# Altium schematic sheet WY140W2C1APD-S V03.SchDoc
size A2; CompanyName: 英集芯科技; DrawnBy: hjz
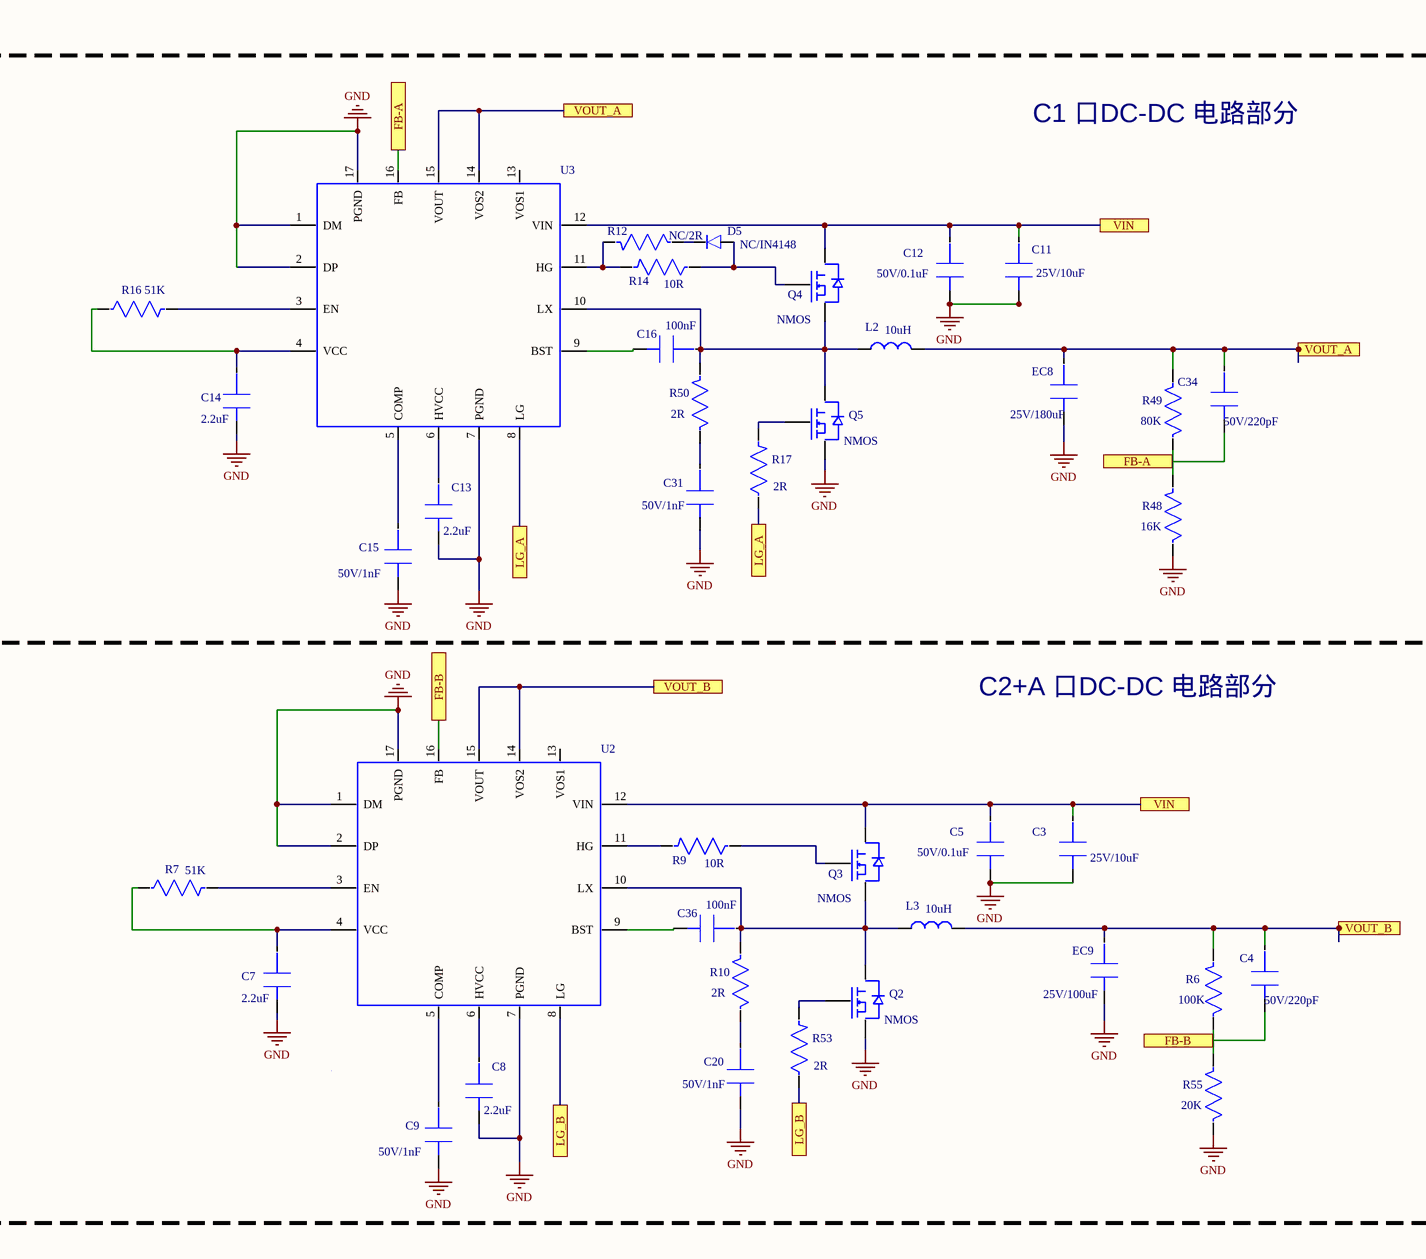
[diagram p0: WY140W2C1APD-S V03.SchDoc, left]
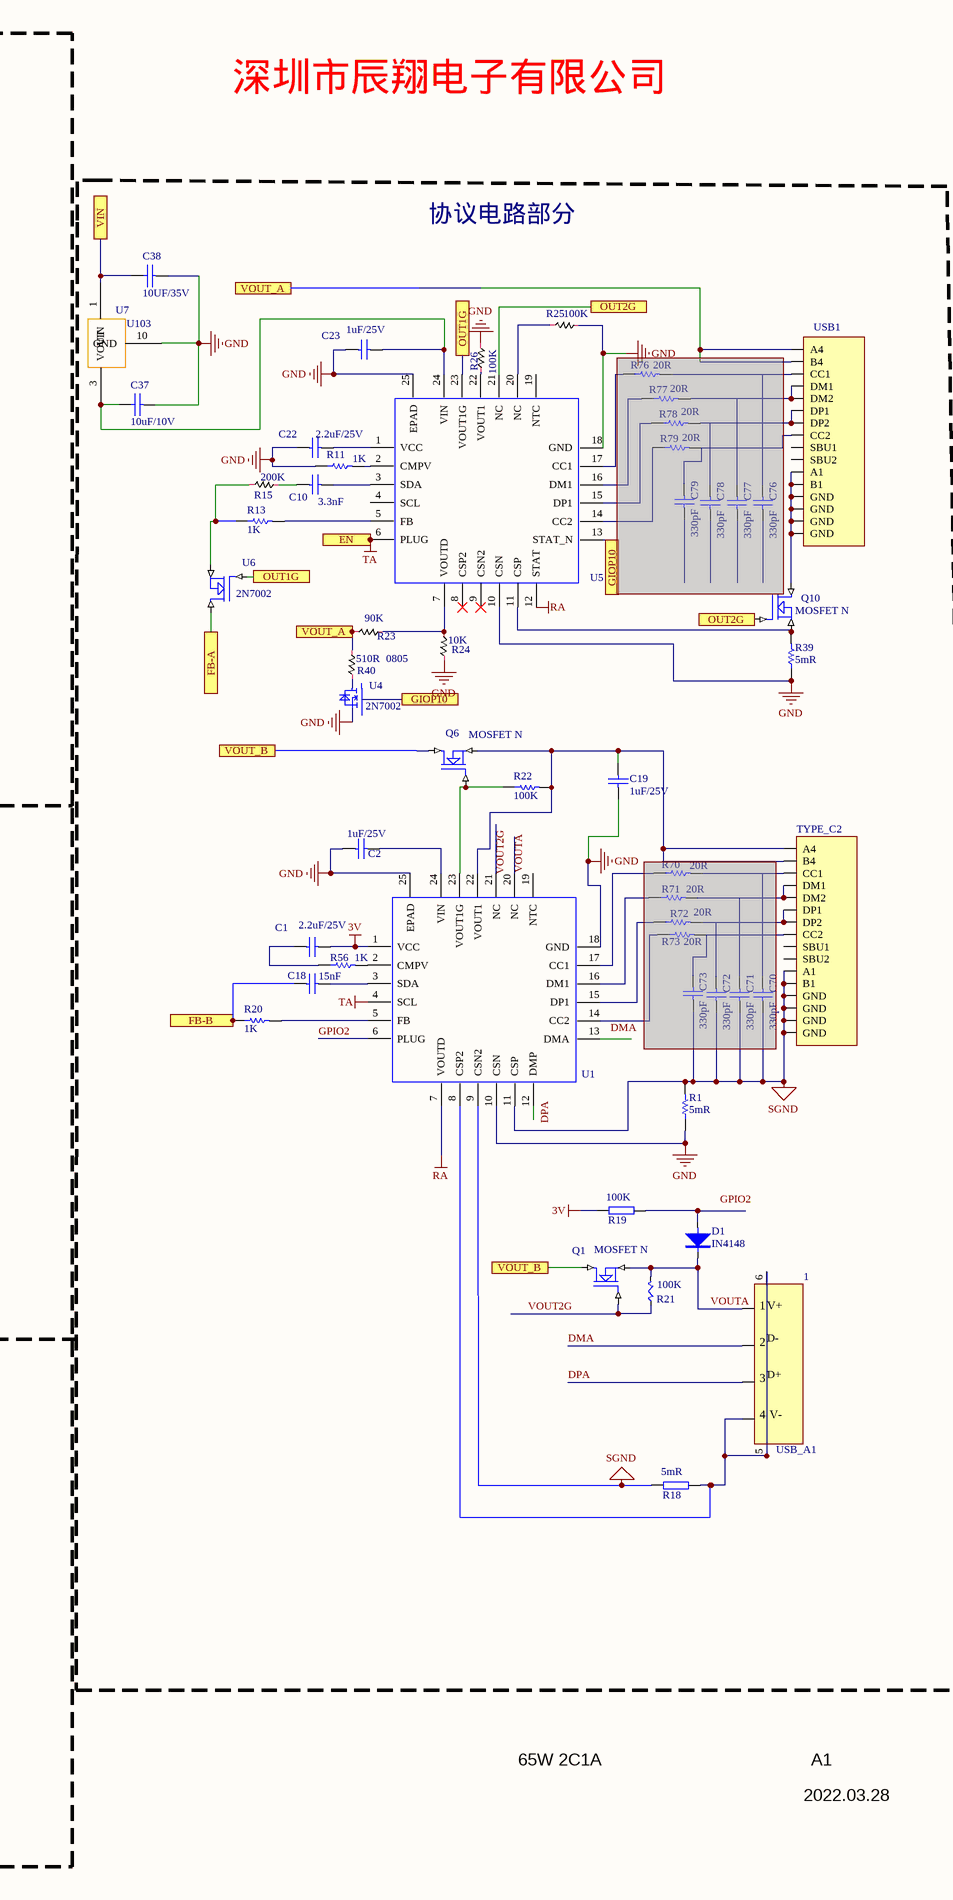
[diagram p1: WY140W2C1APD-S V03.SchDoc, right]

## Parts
1  USB_A1
C1  value 2.2uF/25V  [C0603]  (hidden comment: Cap)
C2  value 1uF/25V  [C0603]  (hidden comment: Cap)
C3  value 25V/10uF  [C0805]  (hidden comment: 0.1uF)
C4  value 50V/220pF  [C0805]  (hidden comment: 0.1uF)
C5  value 50V/0.1uF  [C0805]  (hidden comment: 0.1uF)
C7  2.2uF  [C0603]
C8  2.2uF  [C0603]
C9  value 50V/1nF  [C0603]  (hidden comment: 1nF)
C10  value 3.3nF  [C0603]  (hidden comment: Cap)
C11  value 25V/10uF  [C0805]  (hidden comment: 0.1uF)
C12  value 50V/0.1uF  [C0805]  (hidden comment: 0.1uF)
C13  2.2uF  [C0603]
C14  2.2uF  [C0603]
C15  value 50V/1nF  [C0603]  (hidden comment: 1nF)
C16  value 100nF  [C0603]  (hidden comment: 2.2uF)
C18  value 15nF  [C0603]  (hidden comment: Cap)
C19  value 1uF/25V  [C0603]  (hidden comment: Cap)
C20  value 50V/1nF  [C0603]  (hidden comment: 1nF)
C22  value 2.2uF/25V  [C0603]  (hidden comment: Cap)
C23  value 1uF/25V  [C0603]  (hidden comment: Cap)
C31  value 50V/1nF  [C0603]  (hidden comment: 1nF)
C34  value 50V/220pF  [C0805]  (hidden comment: 0.1uF)
C36  value 100nF  [C0603]  (hidden comment: 2.2uF)
C37  10uF/10V  [1206A]
C38  10UF/35V  [1206A]
C70  value 330pF  [C0603]  (hidden comment: Cap)  (masked out: inside a compile mask, not in the netlist)
C71  value 330pF  [C0603]  (hidden comment: Cap)  (masked out: inside a compile mask, not in the netlist)
C72  value 330pF  [C0603]  (hidden comment: Cap)  (masked out: inside a compile mask, not in the netlist)
C73  value 330pF  [C0603]  (hidden comment: Cap)  (masked out: inside a compile mask, not in the netlist)
C76  value 330pF  [C0603]  (hidden comment: Cap)  (masked out: inside a compile mask, not in the netlist)
C77  value 330pF  [C0603]  (hidden comment: Cap)  (masked out: inside a compile mask, not in the netlist)
C78  value 330pF  [C0603]  (hidden comment: Cap)  (masked out: inside a compile mask, not in the netlist)
C79  value 330pF  [C0603]  (hidden comment: Cap)  (masked out: inside a compile mask, not in the netlist)
D1  IN4148
D5  value NC/IN4148  [SOD323]  (hidden comment: 1N4148)
EC8  value 25V/180uF  [C6.5 x12]  (hidden comment: 100uF)
EC9  value 25V/100uF  [C6.5 x12]  (hidden comment: 100uF)
L2  10uH  [L1406]
L3  10uH  [L1406]
Q1  MOSFET N
Q2  NMOS  [DFN5X6]
Q3  NMOS  [DFN5X6]
Q4  NMOS  [DFN5X6]
Q5  NMOS  [DFN5X6]
Q6  MOSFET N
Q10  MOSFET N
R1  value 5mR  [R1206]  (hidden comment: Res1)
R6  value 100K  [R0603]  (hidden comment: 2R)
R7  51K  [R0603]
R9  10R  [R0603]
R10  2R  [R0603]
R11  value 1K  [R0603]  (hidden comment: Res1)
R12  NC/2R  [R0603]
R13  value 1K  [R0603]  (hidden comment: Res1)
R14  10R  [R0603]
R15  200K
R16  51K  [R0603]
R17  2R  [R0603]
R18  5mR  [1206R/L]
R19  100K  [0603R/L]
R20  value 1K  [R0603]  (hidden comment: Res1)
R21  100K  [RES-0603]
R22  value 100K  [R0402]  (hidden comment: Res1)
R23  90K
R24  10K
R25  100K
R26  100K
R39  value 5mR  [R1206]  (hidden comment: Res1)
R40  510R  0805
R48  value 16K  [R0603]  (hidden comment: 2R)
R49  value 80K  [R0603]  (hidden comment: 2R)
R50  2R  [R0603]
R53  2R  [R0603]
R55  value 20K  [R0603]  (hidden comment: 2R)
R56  value 1K  [R0603]  (hidden comment: Res1)
R70  value 20R  [R0603]  (hidden comment: Res1)
R71  value 20R  [R0603]  (hidden comment: Res1)  (masked out: inside a compile mask, not in the netlist)
R72  value 20R  [R0603]  (hidden comment: Res1)  (masked out: inside a compile mask, not in the netlist)
R73  value 20R  [R0603]  (hidden comment: Res1)  (masked out: inside a compile mask, not in the netlist)
R76  value 20R  [R0603]  (hidden comment: Res1)  (masked out: inside a compile mask, not in the netlist)
R77  value 20R  [R0603]  (hidden comment: Res1)  (masked out: inside a compile mask, not in the netlist)
R78  value 20R  [R0603]  (hidden comment: Res1)  (masked out: inside a compile mask, not in the netlist)
R79  value 20R  [R0603]  (hidden comment: Res1)  (masked out: inside a compile mask, not in the netlist)
TYPE_C2  (no value)  [Type-c-1]
U1  (no value)  [QFN24-0.5]
U2  CX6650_QFN16  [QFN16]  (value not drawn)
U3  CX6650_QFN16  [QFN16]  (value not drawn)
U4  2N7002
U5  (no value)  [QFN24-0.5]
U6  2N7002
U7  U103
USB1  (no value)  [Type-c-1]

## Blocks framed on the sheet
协议电路部分: 1 C1 C2 C10 C18 C19 C22 C23 C37 C38 C70-C73 C76-C79 D1 Q1 Q6 Q10 R1 R11 R13 R15 R18-R26 R39 R40 R56 R70-R73 R76-R79 TYPE_C2 U1 U4-U7 USB1

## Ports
EN, FB-A, FB-B, GIOP10, LG_A, LG_B, OUT1G, OUT2G, VIN, VOUT_A, VOUT_B

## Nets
3V: C1.1 R19.2 U1.1(VCC)
GND: C2.2 C3.2 C5.2 C7.2 C8.2 C9.2 C11.2 C12.2 C13.2 C14.2 C15.2 C19.2 C20.2 C22.2 C23.2 C31.2 C37.1 C38.1 EC8.2 EC9.2 Q2.4(S) Q5.4(S) R1.1 R11.1 R24.1 R25.1 R26.1 R39.1 R48.1 R55.1 U1.10(CSN) U1.18(GND) U1.25(EPAD) U2.1(DM) U2.2(DP) U2.7(PGND) U2.17(PGND) U3.1(DM) U3.2(DP) U3.7(PGND) U3.17(PGND) U5.10(CSN) U5.18(GND) U5.25(EPAD) U7.10(GND)
RA: U1.7(VOUTD) U5.12(STAT)
SGND: R1.2 R18.2 TYPE_C2.A1 TYPE_C2.B1 TYPE_C2.GND U1.9(CSN2) U1.11(CSP)
TA: U1.4(SCL) U5.6(PLUG) ; port EN
DMA: 1.2
DPA: 1.3
FB-A: C34.2 U3.16(FB) U6.2(D) ; port FB-A
FB-B: C4.2 C18.2 R20.1 U2.16(FB) ; port FB-B
GIOP10: U5.13(STAT_N) ; port GIOP10
GPIO2: U1.6(PLUG)
LG_A: R17.1 U3.8(LG) ; port LG_A
LG_B: R53.1 U2.8(LG) ; port LG_B
OUT1G: U5.23(VOUT1G) U6.1(G) ; port OUT1G
OUT2G: Q10.1(G) U5.21(NC) ; port OUT2G
VIN: C3.1 C5.1 C11.1 C12.1 C38.2 Q3.5(D) Q4.5(D) U2.12(VIN) U3.12(VIN) U7.1(VIN) ; port VIN
VOUT2G: Q1.1(G) R21.1
VOUT_A: C34.1 EC8.1 L2.1 R23.2 R40.2 R49.2 U3.14(VOS2) U3.15(VOUT) USB1.A4 USB1.B4 ; port VOUT_A
VOUT_B: C4.1 EC9.1 L3.1 Q1.2(D) Q6.2(D) R6.2 U2.14(VOS2) U2.15(VOUT) ; port VOUT_B
VOUTA: 1.1 D1.2(K) Q1.3(S) R21.2
Net1_4: 1.4 1.5 1.6 R18.1 U1.8(CSP2)
NetC1_2: C1.2 R56.1
NetC2_1: C2.1 U1.24(VIN)
NetC7_1: C7.1 R7.1 U2.4(VCC)
NetC8_1: C8.1 U2.6(HVCC)
NetC9_1: C9.1 U2.5(COMP)
NetC10_1: C10.1 U5.3(SDA)
NetC10_2: C10.2 R15.1
NetC13_1: C13.1 U3.6(HVCC)
NetC14_1: C14.1 R16.1 U3.4(VCC)
NetC15_1: C15.1 U3.5(COMP)
NetC16_1: C16.1 L2.2 Q4.4(S) Q5.5(D) R50.2 U3.10(LX)
NetC16_2: C16.2 U3.9(BST)
NetC18_1: C18.1 U1.3(SDA)
NetC19_1: C19.1 Q6.3(S) R22.2 TYPE_C2.A4 TYPE_C2.B4 U1.22(VOUT1)
NetC20_1: C20.1 R10.1
NetC22_1: C22.1 U5.1(VCC)
NetC23_1: C23.1 C37.2 U5.24(VIN) U7.3(VOUT)
NetC31_1: C31.1 R50.1
NetC36_1: C36.1 L3.2 Q2.5(D) Q3.4(S) R10.2 U2.10(LX)
NetC36_2: C36.2 U2.9(BST)
NetD1_1: D1.1(A) R19.1
NetD5_1: D5.1 Q4.1(G) R14.1
NetD5_2: D5.2 R12.1
NetQ2_1: Q2.1(G) R53.2
NetQ3_1: Q3.1(G) R9.1
NetQ5_1: Q5.1(G) R17.2
NetQ6_1: Q6.1(G) R22.1 U1.23(VOUT1G)
NetQ10_2: Q10.2(D) USB1.A1 USB1.B1 USB1.GND
NetQ10_3: Q10.3(S) R39.2 U5.11(CSP)
NetR6_1: R6.1 R55.2
NetR7_2: R7.2 U2.3(EN)
NetR9_2: R9.2 U2.11(HG)
NetR11_2: R11.2 U5.2(CMPV)
NetR12_2: R12.2 R14.2 U3.11(HG)
NetR13_1: R13.1 R15.2 U6.3(S)
NetR13_2: R13.2 U5.5(FB)
NetR16_2: R16.2 U3.3(EN)
NetR20_2: R20.2 U1.5(FB)
NetR23_1: R23.1 R24.2 U5.7(VOUTD)
NetR25_2: R25.2 U5.20(NC)
NetR26_2: R26.2 U5.22(VOUT1)
NetR48_2: R48.2 R49.1
NetR56_2: R56.2 U1.2(CMPV)
NetR70_1: R70.1 U1.17(CC1)
NetR70_2: R70.2 TYPE_C2.CC1
NetTYPE_C2_DM1: TYPE_C2.DM1 TYPE_C2.DM2
NetTYPE_C2_DP1: TYPE_C2.DP1 TYPE_C2.DP2
NetUSB1_DM1: USB1.DM1 USB1.DM2
NetUSB1_DP1: USB1.DP1 USB1.DP2

Not connected (* = marked no-connect by the designer): R40 1; TYPE_C2 CC2 SBU1 SBU2; U1 12(DMP) 13(DMA) 14(CC2) 15(DP1) 16(DM1) 19(NTC) 20(NC) 21(NC); U2 13(VOS1); U3 13(VOS1); U4 1(G) 2(S) 3(D); U5 4(SCL) 8(CSP2)* 9(CSN2)* 14(CC2) 15(DP1) 16(DM1) 17(CC1) 19(NTC); USB1 CC1 CC2 SBU1 SBU2

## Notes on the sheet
- 深圳市辰翔电子有限公司
- C1 口DC-DC 电路部分
- C2+A 口DC-DC 电路部分
- 65W 2C1A
- 2022.03.28
- A1
- Labels drawn without touching a wire or pin: DMA, DPA, GPIO2, VOUT2G, VOUTA

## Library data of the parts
1 = USB
C1 C2 C10 C18 C19 C22 C23 C70-C73 C76-C79 = Cap: Capacitor
C3-C5 C7-C9 C11-C16 C20 C31 C34 C36 = C0603: Capacitor; Part Number: CC05CGXXXX; Manufacturer #1: KEMET; Sim.Analog.Order: Model$; Sim.Analog.Prefix: C; Tolerance: ???; Voltage Rating: 10v; PCB DECAL: 0603C
C37 C38 = CAP: Capacitor
D1 = DIODE
D5 = DIODE: Part_Field_Name_11: Part Field 11; Part_Field_Name_10: Part Field 10; Part_Field_Name_1: Part Field 1; PCB DECAL: SOD-123A
EC8 EC9 = C0805: Capacitor; Part Number: CC05CGXXXX; Manufacturer #1: KEMET; Sim.Analog.Order: Model$; Sim.Analog.Prefix: C; Tolerance: ???; Voltage Rating: 10v; PCB DECAL: CAP-5-5
L2 L3 = INDUCTOR: Code_IEC: 1005
Q2-Q5 = NMOS: value: 2N7002 SOT23; value1: 2N7002
R1 R11 R13 R20 R22 R39 R56 R70-R73 R76-R79 = Res1: Resistor
R6 R7 R9 R10 R12 R14 R16 R17 R48-R50 R53 R55 = R0603: Resistor; PCB DECAL: 0603R
R15 R23-R26 R40 = RSE2
R18 R19 = R: 贴片电阻
R21 = RES
TYPE_C2 U7 USB1 = Component_1
U1 U5 = IP2723T/IP2726: PCB DECAL: QFN24_0.5
U2 U3 = GC1022_QFN16: PCB DECAL: QFN12
U4 = NMOS_1: value: 2N7002 SOT23; PCB DECAL: SOT23
U6 = MOSFET N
